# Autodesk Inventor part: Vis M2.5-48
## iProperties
Author: Philippe
Created: 2002-08
Part Number: Vis M2.5-48
Material: EN-CW 612N
Document SubType Name: Modélisation
Designer: Philippe
Control State: 0
Master: False
Checked Out: False
PropertySet Name: Design Tracking Control
Shininess: 20.0
Angle Display Precision: 2
Document Length Units: 11269
Document Angle Units: 11283
Document Time Units: 11279
Document Mass Units: 11290
Document Length Units Precision: 3
Document Angle Units Precision: 2
Compacted: False
PropertySet Name: _Private Model Information
Density: 8.47
Volumn: 0.24798947009274533
Area: 4.205344765727714
PropertySet Name: Model Information
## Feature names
1. Révolution1 [Revolution]
2. Chanfrein1 [Chamfer]
3. Lissage1
